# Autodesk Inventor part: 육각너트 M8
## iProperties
IsCustomPart: 1
Created: 2009-02
Part Number: 육각너트 M8
Material: 강, 연강
Description: 6각 너트 및 6각 가는 너트
Document SubType Name: Modeling
Standard: KS B 1012
Designer: SeoGD™[esajin.kr]
Standards Organization: KS
Language: ko-KR
Size Designation: C M8
Categories: <MemberInstance><Categories><Category DisplayName="조임쇠" InternalName="e4da775c-781d-43d5-af7c-5136215cf5a6" Mnemonic="FSTN"><Category DisplayName="너트" InternalN
Density: 1 g/cm^3
Author: SeoGD™[esajin.kr]
